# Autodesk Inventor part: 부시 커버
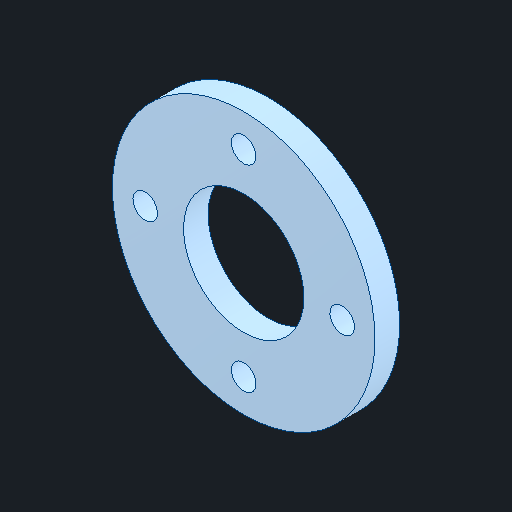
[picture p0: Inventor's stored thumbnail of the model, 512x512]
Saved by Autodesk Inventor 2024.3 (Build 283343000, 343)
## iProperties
Created: 2024-05
Part Number: 부시 커버
Material: 강철, 연강
Document SubType Name: Modeling
Designer: MyPc
Density: 7.85 g/cm^3
Appearance: 기본값
Author: jhkim
Sending System: Autodesk Inventor 2025
Preprocessor: ST-DEVELOPER v20
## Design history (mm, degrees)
node "부시 커버1"
node "솔리드2"
node "솔리드1"
